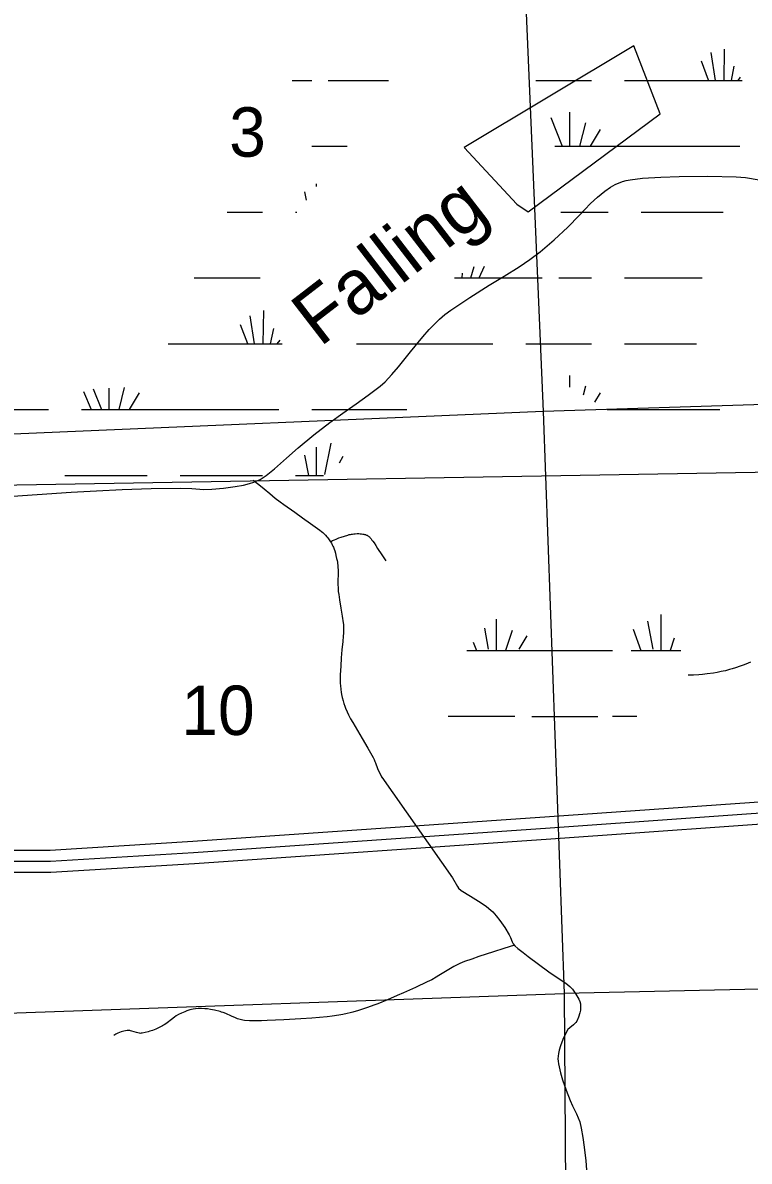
# Model space of a CAD drawing. Extents: x 2480962 to 2688785, y 277103 to 599240.
# Drawn here: x 2566050 to 2572670, y 453472 to 463845 of the extents above; entities that cross this region are included whole.
import ezdxf

# ---------------------------------------------------------------- set-up
doc = ezdxf.new("R2010")
doc.units = 0
for name, color, linetype in [('Divided_Highway', 7, 'Continuous'), ('Interstate Divided Highway Outline and Fill', 7, 'Continuous'), ('Interstate Highway Center Lines', 7, 'Continuous'), ('Lakes and Ponds Text', 7, 'Continuous'), ('Level 31', 7, 'Continuous'), ('Narrow River Creek and Branch and Slough', 7, 'Continuous'), ('Section Lines', 7, 'Continuous'), ('Section Numbers', 7, 'Continuous'), ('Swamps', 7, 'Continuous')]:
    doc.layers.add(name, color=color, linetype=linetype)

msp = doc.modelspace()

# ---------------------------------------------------------------- linework, layer by layer
at = {"layer": 'Divided_Highway'}
msp.add_line((2560538.616, 459542.689), (2600001.432, 460214.017), dxfattribs=at)
at = {"layer": 'Interstate Divided Highway Outline and Fill'}
for points in [[(2581663.622, 458398.875), (2578742.414, 457750.607), (2576053.77, 457142.461), (2575560.35, 457039.002), (2575035.889, 456951.592), (2574184.482, 456840.193), (2573323.038, 456784.359), (2570849.716, 456608.265), (2567600.738, 456384.197), (2566299.586, 456304.372), (2565629.772, 456304.372)], [(2565630.922, 456104.372), (2566305.715, 456104.372), (2567613.741, 456184.619), (2570863.698, 456408.754), (2573336.608, 456584.819), (2574203.945, 456641.035), (2575065.311, 456753.737), (2575597.327, 456842.407), (2576096.356, 456947.042), (2578786.14, 457555.445), (2581707.57, 458203.762)]]:
    msp.add_lwpolyline(points, dxfattribs=at)
at = {"layer": 'Interstate Highway Center Lines'}
msp.add_lwpolyline([(2565630.347, 456204.372), (2566302.651, 456204.372), (2567607.24, 456284.408), (2570856.707, 456508.509), (2573329.823, 456684.589), (2574194.214, 456740.614), (2575050.6, 456852.665), (2575578.839, 456940.705), (2576075.063, 457044.752), (2578764.277, 457653.026), (2581685.596, 458301.319)], dxfattribs=at)
at = {"layer": 'Level 31'}
msp.add_lwpolyline([(2570072.935, 462707.261), (2570553.452, 462192.083), (2570656.42, 462123.392), (2571857.712, 463016.367), (2571617.454, 463634.581)], close=True, dxfattribs=at)
at = {"layer": 'Narrow River Creek and Branch and Slough'}
for points in [[(2565873.17, 459524.639), (2566181.912, 459546.191), (2566490.717, 459566.926), (2566722.954, 459579.907), (2566955.329, 459590.75), (2567219.408, 459600.017), (2567483.511, 459605.112), (2567591.964, 459599.976), (2567700.365, 459593.009), (2567771.705, 459594.112), (2567878.53, 459603.367), (2567985.279, 459619.019), (2568060.256, 459632.867), (2568115.825, 459646.38), (2568156.487, 459659.278), (2568214.883, 459684.575), (2568268.959, 459718.894), (2568344.586, 459780.827), (2568452.133, 459877.248), (2568560.648, 459971.954), (2568702.7, 460089.485), (2568847.407, 460203.819), (2568967.049, 460288.384), (2569087.679, 460371.554), (2569198.645, 460450.577), (2569306.909, 460533.65), (2569351.914, 460574.488), (2569413.75, 460641.358), (2569473.048, 460710.666), (2569584.087, 460847.29), (2569695.709, 460983.647), (2569754.628, 461049.296), (2569847.886, 461142.901), (2569897.807, 461185.946), (2569950.596, 461225.52), (2570124.556, 461341.438), (2570300.836, 461453.199), (2570436.884, 461537.219), (2570572.805, 461621.479), (2570671.148, 461686.518), (2570766.062, 461756.741), (2570894.05, 461866.433), (2571015.931, 461982.693), (2571120.064, 462089.715), (2571223.713, 462197.368), (2571286.457, 462255.842), (2571353.93, 462310.435), (2571407.311, 462347.085), (2571449.315, 462370.708), (2571515.315, 462398.354), (2571549.597, 462408.07), (2571584.695, 462414.677), (2571696.754, 462427.686), (2571864.949, 462438.951), (2572033.371, 462443.504), (2572292.439, 462445.831), (2572551.252, 462441.856), (2572634.891, 462434.179), (2572759.837, 462413.786)], [(2568150.768, 459677.282), (2568200.324, 459637.249), (2568249.854, 459597.182), (2568300.668, 459555.747), (2568351.635, 459514.491), (2568394.932, 459481.154), (2568427.968, 459456.897), (2568528.167, 459385.588), (2568600.354, 459334.039), (2568672.562, 459282.52), (2568715.414, 459251.696), (2568758.142, 459220.661), (2568772.214, 459209.886), (2568784.053, 459199.944), (2568794.053, 459190.849), (2568802.532, 459182.587), (2568809.745, 459175.126), (2568821.911, 459161.544), (2568830.658, 459150.918), (2568843.179, 459134.273), (2568854.993, 459116.775), (2568863.945, 459101.862), (2568870.988, 459088.615), (2568876.595, 459076.875), (2568881.108, 459066.49), (2568888.204, 459048.068), (2568892.927, 459034.047), (2568899.193, 459012.695), (2568904.652, 458990.967), (2568910.467, 458964.765), (2568914.325, 458945.102), (2568916.87, 458930.327), (2568918.553, 458919.222), (2568920.676, 458902.511), (2568922.262, 458885.718), (2568923.692, 458858.045), (2568924.008, 458833.779), (2568922.439, 458748.742), (2568922.368, 458727.518), (2568923.274, 458695.758), (2568924.356, 458679.922), (2568925.963, 458664.124), (2568929.686, 458635.764), (2568937.34, 458586.294), (2568949.954, 458512.194), (2568956.015, 458475.063), (2568961.448, 458437.798), (2568969.95, 458377.246), (2568971.691, 458362.1), (2568972.742, 458350.737), (2568973.787, 458333.687), (2568974.04, 458316.63), (2568973.038, 458284.27), (2568971.282, 458255.954), (2568966.823, 458206.394), (2568958.731, 458132.036), (2568954.964, 458094.847), (2568951.945, 458057.649), (2568947.355, 457981.083), (2568943.934, 457904.461), (2568943.255, 457874.717), (2568943.388, 457848.71), (2568944.116, 457825.971), (2568945.259, 457806.089), (2568948.488, 457771.331), (2568952.018, 457745.297), (2568955.335, 457725.793), (2568961.453, 457696.574), (2568969.03, 457667.402), (2568977.194, 457640.835), (2568985.081, 457618.089), (2568992.524, 457598.537), (2569006.699, 457565.015), (2569018.23, 457540.377), (2569036.848, 457504.074), (2569056.901, 457468.364), (2569100.442, 457395.197), (2569143.892, 457322.088), (2569193.552, 457236.231), (2569217.963, 457193.064), (2569241.888, 457149.614), (2569251.024, 457131.343), (2569258.164, 457114.969), (2569263.92, 457100.416), (2569282.395, 457048.686), (2569322.293, 456969.585)], [(2572682.88, 458019.308), (2572659.727, 458009.526), (2572624.526, 457995.825), (2572588.729, 457982.983), (2572545.82, 457968.45), (2572513.639, 457958.212), (2572489.384, 457951.008), (2572452.627, 457941.112), (2572434.01, 457936.632), (2572415.193, 457932.499), (2572377.658, 457925.142), (2572344.804, 457919.488), (2572287.281, 457911.371), (2572244.117, 457906.788), (2572211.732, 457904.206), (2572163.137, 457901.728), (2572114.521, 457900.94)], [(2569321.973, 456970.039), (2569967.581, 456053.554), (2570011.856, 455975.401), (2570022.46, 455960.616), (2570045.726, 455939.038), (2570129.574, 455887.707), (2570201.993, 455842.035), (2570273.793, 455795.191), (2570298.786, 455775.571), (2570333.315, 455742.893), (2570365.096, 455707.043), (2570397.498, 455665.463), (2570442.134, 455600.956), (2570484.223, 455534.932), (2570496.369, 455509.815), (2570511.1, 455470.013), (2570520.489, 455451.545), (2570533.441, 455435.504), (2570563.051, 455409.204), (2570609.342, 455372.635), (2570656.618, 455337.349), (2570750.123, 455267.47), (2570843.891, 455198.074), (2570920.915, 455146.578), (2570998.852, 455095.189), (2571035.214, 455064.525), (2571059.437, 455038.245), (2571091.121, 454995.108), (2571117.538, 454949.458), (2571126.773, 454926.357), (2571131.511, 454904.675), (2571133.315, 454884.908), (2571131.76, 454849.365), (2571127.139, 454822.642), (2571115.609, 454783.907), (2571099.755, 454748.604), (2571090.634, 454735.067), (2571069.797, 454714.934), (2571034.508, 454686.989), (2571018.668, 454671.061), (2571006.253, 454652), (2570972.468, 454579.481), (2570950.634, 454524.568), (2570938.044, 454483.299), (2570931.498, 454452.387), (2570927.479, 454406.218), (2570928.518, 454383.272), (2570931.859, 454360.452), (2570951.658, 454276.235), (2570969.953, 454213.09), (2571001.88, 454118.574), (2571037.87, 454024.511), (2571060.247, 453975.607), (2571096.621, 453904.612), (2571112.807, 453868.44), (2571125.653, 453830.75), (2571139.651, 453773.444), (2571155.261, 453686.678), (2571166.508, 453599.239), (2571179.921, 453475.545), (2571191.78, 453351.628)], [(2570530.43, 455441.586), (2570434.595, 455410.644), (2570338.862, 455379.382), (2570207.097, 455336.175), (2570141.463, 455313.807), (2570076.137, 455290.421), (2570053.602, 455281.572), (2570032.836, 455272.503), (2570013.65, 455263.4), (2569978.291, 455245.013), (2569947.868, 455227.818), (2569842.979, 455164.125), (2569816.639, 455148.414), (2569776.641, 455125.854), (2569756.331, 455115.219), (2569735.759, 455105.128), (2569628.601, 455055.107), (2569520.754, 455006.435), (2569462.05, 454980.898), (2569373.606, 454943.677), (2569284.619, 454907.377), (2569250.554, 454893.909), (2569190.553, 454871.625), (2569145.142, 454856.182), (2569110.805, 454845.425), (2569058.783, 454830.784), (2569032.51, 454824.199), (2569006.046, 454818.144), (2568966.101, 454810.008), (2568931.086, 454803.734), (2568869.668, 454794.423), (2568823.491, 454788.636), (2568754.052, 454781.483), (2568684.418, 454775.669), (2568582.81, 454768.578), (2568430.373, 454759.97), (2568277.915, 454752.844), (2568226.409, 454750.975), (2568187.74, 454750.315), (2568158.733, 454750.391), (2568115.24, 454751.652), (2568071.801, 454754.576), (2568057.122, 454756.421), (2568043.579, 454759.036), (2568031.051, 454762.177), (2568007.93, 454769.589), (2567988.002, 454777.354), (2567953.517, 454792.721), (2567901.771, 454816.4), (2567875.438, 454826.799), (2567862.064, 454831.29), (2567848.518, 454835.177), (2567798.644, 454847.242), (2567760.779, 454854.75), (2567732.275, 454859.136), (2567710.903, 454861.567), (2567678.951, 454863.595), (2567663.059, 454863.788), (2567647.247, 454863.381), (2567624.357, 454861.4), (2567604.439, 454858.225), (2567587.102, 454854.433), (2567572.005, 454850.398), (2567545.762, 454841.876), (2567526.233, 454834.397), (2567497.206, 454821.692), (2567468.517, 454807.531), (2567448.658, 454796.137), (2567432.344, 454785.196), (2567405.317, 454764.66), (2567365.556, 454733.12), (2567344.669, 454718.251), (2567333.699, 454711.291), (2567322.276, 454704.742), (2567299.948, 454693.149), (2567280.267, 454683.746), (2567262.933, 454676.093), (2567232.337, 454664.02), (2567209.166, 454656.087), (2567191.658, 454650.781), (2567165.18, 454643.872), (2567138.439, 454638.249), (2567129.917, 454637.209), (2567121.899, 454637.122), (2567114.359, 454637.72), (2567100.175, 454640.284), (2567087.724, 454643.67), (2567044.052, 454657.843), (2567033.155, 454660.549), (2567024.997, 454662.013), (2567012.797, 454663.024), (2567000.648, 454662.267), (2566985.012, 454659.652), (2566971.451, 454656.805), (2566947.994, 454650.41), (2566930.638, 454644.296), (2566917.758, 454638.893), (2566898.665, 454629.361), (2566879.851, 454617.968)]]:
    msp.add_lwpolyline(points, dxfattribs=at)
at = {"layer": 'Section Lines'}
for p, q in [((2570563.563, 465681.678), (2570792.999, 460303.215)), ((2576106.481, 460473.255), (2570792.999, 460303.215)), ((2570792.999, 460303.215), (2565468.536, 460074.864)), ((2570792.999, 460303.215), (2570984.082, 455000.634)), ((2576266.606, 455113.189), (2570984.082, 455000.634)), ((2560288.246, 454622.652), (2570984.082, 455000.635)), ((2570984.082, 455000.634), (2571018.838, 449724.408))]:
    msp.add_line(p, q, dxfattribs=at)
at = {"layer": 'Swamps'}
for p, q in [((2572362.362, 463319.814), (2572322.968, 463573.047)), ((2572300.04, 463320.736), (2572233.969, 463493.529)), ((2571534.363, 463319.736), (2572134.361, 463319.746)), ((2571033.028, 463030.733), (2571033.031, 462719.729)), ((2571178.015, 462934.077), (2571124.406, 462719.63)), ((2571310.92, 462873.669), (2571221.203, 462719.862)), ((2572134.368, 462719.748), (2572584.367, 462719.755)), ((2567934.391, 462119.68), (2568234.39, 462119.685)), ((2571684.378, 462119.742), (2572134.376, 462119.75)), ((2572134.376, 462119.75), (2572434.375, 462119.755)), ((2570209.182, 461519.851), (2570258.065, 461628.484)), ((2570934.388, 461519.731), (2571234.387, 461519.736)), ((2571534.386, 461519.741), (2572134.383, 461519.751)), ((2568240.57, 460919.707), (2568246.297, 461223.421)), ((2568100.086, 460920.673), (2568034.015, 461093.466)), ((2568162.408, 460919.751), (2568123.014, 461172.985)), ((2570634.397, 460919.728), (2571234.394, 460919.738)), ((2571534.393, 460919.743), (2572134.391, 460919.753)), ((2566603.513, 460485.679), (2566674.326, 460319.664)), ((2567110.967, 460473.606), (2567021.249, 460319.799)), ((2565834.422, 460319.65), (2566284.421, 460319.657)), ((2566584.419, 460319.662), (2567934.414, 460319.685)), ((2567934.414, 460319.685), (2568384.413, 460319.693)), ((2570792.999, 460303.215), (2570984.082, 455000.635)), ((2568725.362, 459978.261), (2568725.365, 459719.7)), ((2568616.622, 459905.766), (2568653.833, 459719.721)), ((2566434.428, 459719.662), (2567184.425, 459719.674)), ((2567484.424, 459719.679), (2567934.422, 459719.687)), ((2567934.422, 459719.687), (2568234.421, 459719.692)), ((2571744.426, 458392.484), (2571792.758, 458138.754)), ((2571865.248, 458452.897), (2571865.252, 458126.673)), ((2570510.242, 458307.886), (2570449.833, 458126.649)), ((2571611.522, 458319.987), (2571684.018, 458126.67)), ((2570643.147, 458259.559), (2570570.655, 458138.733)), ((2570693.939, 458126.653), (2571424.792, 458126.666)), ((2569925.702, 457526.634), (2570534.928, 457526.644)), ((2570690.784, 457524.029), (2571290.781, 457524.039))]:
    msp.add_line(p, q, dxfattribs=at)
for points in [[(2572440.524, 463319.77), (2572445.914, 463605.624)], [(2572507.622, 463319.562), (2572534.395, 463448.075)], [(2568504.516, 463319.686), (2568684.373, 463319.689)], [(2568834.373, 463319.691), (2569382.205, 463319.7)], [(2570726.486, 463319.723), (2571234.364, 463319.731)], [(2572134.361, 463319.746), (2572606.462, 463319.754)], [(2572569.818, 463319.255), (2572590.771, 463347.692)], [(2570863.877, 462982.401), (2570966.898, 462719.728)], [(2568684.381, 462719.69), (2569005.387, 462719.696)], [(2570899.798, 462719.727), (2572134.368, 462719.748)], [(2568725.331, 462378.254), (2568725.332, 462351.691)], [(2568616.592, 462305.759), (2568631.947, 462228.981)], [(2567911.473, 462119.679), (2567934.391, 462119.68)], [(2568534.389, 462119.69), (2568548.775, 462119.69)], [(2570952.896, 462119.73), (2571384.379, 462119.737)], [(2570132.586, 461519.928), (2570162.403, 461624.294)], [(2567611.483, 461519.676), (2567934.399, 461519.681)], [(2567934.399, 461519.681), (2568212.563, 461519.686)], [(2569983.131, 461519.716), (2570784.388, 461519.729)], [(2569984.9, 461519.798), (2569984.743, 461520.657)], [(2570055.9, 461519.749), (2570058.289, 461563.56)], [(2572134.383, 461519.751), (2572242.191, 461519.753)], [(2568307.668, 460919.499), (2568336.977, 461060.191)], [(2567376.387, 460919.674), (2567934.407, 460919.683)], [(2567934.407, 460919.683), (2568412.662, 460919.691)], [(2568369.864, 460919.193), (2568394.743, 460952.958)], [(2569090.524, 460919.703), (2570334.398, 460919.723)], [(2572134.391, 460919.753), (2572191.249, 460919.754)], [(2571033.058, 460630.74), (2571033.059, 460525.524)], [(2566692.501, 460509.474), (2566766.944, 460319.666)], [(2566833.075, 460515.515), (2566833.078, 460319.667)], [(2566974.961, 460521.611), (2566924.452, 460319.567)], [(2571178.045, 460534.084), (2571157.261, 460450.948)], [(2571310.951, 460473.676), (2571261.266, 460388.501)], [(2568684.412, 460319.698), (2569551.257, 460319.712)], [(2571375.78, 460319.742), (2572134.398, 460319.755)], [(2572134.398, 460319.755), (2572402.792, 460319.76)], [(2568858.266, 460014.509), (2568801.066, 459728.494)], [(2568967.007, 459893.689), (2568933.974, 459832.341)], [(2568534.42, 459719.697), (2568789.812, 459719.701)], [(2568854.993, 459116.775), (2568873.934, 459126.6), (2568890.687, 459134.479), (2568905.481, 459140.887), (2568931.674, 459151.177), (2568951.568, 459158.263), (2568981.804, 459168.162), (2569012.505, 459177.537), (2569024.843, 459180.911), (2569035.736, 459183.39), (2569045.324, 459185.211), (2569053.746, 459186.548), (2569068.524, 459188.334), (2569079.615, 459189.229), (2569096.214, 459189.901), (2569112.7, 459189.816), (2569126.089, 459189.194), (2569138.026, 459188.109), (2569148.509, 459186.631), (2569157.621, 459184.858), (2569165.489, 459182.887), (2569172.252, 459180.807), (2569178.052, 459178.693), (2569183.017, 459176.602), (2569187.266, 459174.578), (2569194.458, 459170.573), (2569199.621, 459167.159), (2569203.348, 459164.355), (2569208.685, 459159.741), (2569213.688, 459154.61), (2569224.065, 459142.484), (2569232.519, 459131.811), (2569239.522, 459122.424), (2569251.102, 459105.893), (2569267.565, 459080.857), (2569284.037, 459055.546), (2569322.256, 458998.318), (2569341.241, 458969.631), (2569359.933, 458940.744)], [(2570365.254, 458410.637), (2570365.257, 458126.648)], [(2570256.56, 458328.786), (2570292.764, 458138.729)], [(2570155.736, 458202.077), (2570184.024, 458126.645)], [(2571986.644, 458237.13), (2571949.827, 458126.674)], [(2570095.712, 458126.643), (2570693.939, 458126.653)], [(2571593.936, 458126.668), (2572047.377, 458126.676)], [(2571425.697, 457526.659), (2571645.71, 457526.663)]]:
    msp.add_lwpolyline(points, dxfattribs=at)

# ---------------------------------------------------------------- texts
at = {"layer": 'Lakes and Ponds Text'}
msp.add_text('Falling', height=500, rotation=37.6271222, dxfattribs=at).set_placement((2568757.747, 460883.612))
at = {"layer": 'Section Numbers'}
for s, rotation, p in [('3', 359.97945, (2567931.08, 462624.75)), ('10', 359.9794583, (2567494.269, 457355.647))]:
    msp.add_text(s, height=450, rotation=rotation, dxfattribs=at).set_placement(p)

doc.saveas('drawing.dxf')
